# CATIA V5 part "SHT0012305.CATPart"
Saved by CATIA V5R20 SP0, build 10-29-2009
Part number: 产品1_AllCATPart
Bounding box of the stored display mesh (mm): x 603.237 to 810.902, y -967.604 to -463.206, z 456.819 to 1311.377
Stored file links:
  C:\Users\gongbo\Desktop\设变_1\设变数据1-富生\主驾\不带侧板\SHT0012305.CATPart
  C:\Users\gongbo\Desktop\设变_1\设变数据1-富生\副驾不带腰托\高头枕\SHT0012236.CATPart

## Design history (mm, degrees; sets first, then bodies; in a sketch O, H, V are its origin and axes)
Body1 (main body)
Body2 "SHT0012305_AllCATPart.1\\头枕主体管\\零件几何体"
  Solid1: solid without history
Body3 "SHT0012305_AllCATPart.1\\侧翼支撑钢丝.1\\几何体.9"
  Solid2 "实体.1": solid without history
Body4 "SHT0012305_AllCATPart.1\\侧翼支撑钢丝.1\\几何体.10"
  Solid3 "实体.1": solid without history
Body5 "SHT0012305_AllCATPart.1\\靠背骨架内衬管.1\\零件几何体"
  Solid4 "实体.1": solid without history
Body6 "SHT0012305_AllCATPart.1\\靠背骨架内衬管.2\\零件几何体"
  Solid5 "实体.1": solid without history
Body7 "SHT0012305_AllCATPart.1\\焊接六角螺母.1\\PartBody"
  Solid6 "实体.1": solid without history
Body8 "SHT0012305_AllCATPart.1\\焊接六角螺母.2\\PartBody"
  Solid7 "实体.1": solid without history
Body9 "SHT0012305_AllCATPart.1\\焊接六角螺母.3\\PartBody"
  Solid8 "实体.1": solid without history
Body10 "SHT0012305_AllCATPart.1\\焊接六角螺母.4\\PartBody"
  Solid9 "实体.1": solid without history
Body11 "SHT0012305_AllCATPart.1\\靠背主体管\\零件几何体"
  Solid10 "实体.1": solid without history
Body12 "SHT0012305_AllCATPart.1\\靠背钢管上横骨架\\零件几何体"
  Solid11 "实体.1": solid without history
Body13 "SHT0012305_AllCATPart.1\\靠背下支撑管\\零件几何体"
  Solid12 "实体.1": solid without history
Body14 "SHT0012305_AllCATPart.1\\靠背支撑板条1\\零件几何体"
  Solid13 "实体.1": solid without history
Body15 "SHT0012305_AllCATPart.1\\腰托固定横衬条1.1\\零件几何体"
  Solid14 "实体.1": solid without history
Body16 "SHT0012305_AllCATPart.1\\腰托固定横衬条1.2\\零件几何体"
  Solid15 "实体.1": solid without history
Body17 "SHT0012305_AllCATPart.1\\腰托固定横衬条1.3\\零件几何体"
  Solid16 "实体.1": solid without history
Body18 "SHT0012305_AllCATPart.1\\支撑钢丝.1\\零件几何体"
  Solid17 "实体.1": solid without history
Body19 "SHT0012305_AllCATPart.1\\支撑钢丝.2\\零件几何体"
  Solid18 "实体.1": solid without history
Body20 "SHT0012305_AllCATPart.1\\支撑框线1\\零件几何体"
  Solid19 "实体.1": solid without history
Body21 "零件1.1\\sht0012236.1\\SHT0012224_AllCATPart.1\\几何体.39"
  Solid20 "实体.1": solid without history
Body22 "ASSY-fujiaditouzhen(wuyaotuo)_AllCATPart.1\\SHT0010244-1.1\\头枕横衬板\\H4 升级副驾.1\\副驾背总成\\H4 升级靠背总成_AllCATPart.1\\靠背骨架总成.1\\头枕盒\\横梁.2"
  Solid21: solid without history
